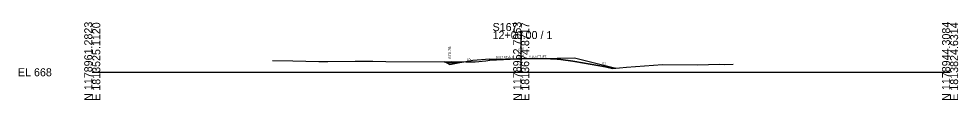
# Model space of a CAD drawing. Extents: x -26 to 6803, y -10 to 1023.
# Drawn here: x -25.7 to 302.8, y 990.3 to 1017.6 of the extents above; entities that cross this region are included whole.
import ezdxf

# ---------------------------------------------------------------- set-up
doc = ezdxf.new("R2010")
doc.units = 0
for name, color, linetype in [('Default', 7, 'Continuous'), ('RD_GPK_XS_Cell', 7, 'Continuous'), ('RD_XS_EarthShd', 7, 'Continuous'), ('RD_XS_ExGround', 7, 'Continuous'), ('RD_XS_Misc_Line', 7, 'Continuous'), ('RD_XS_Pave', 7, 'Continuous'), ('RD_XS_TieSlope', 7, 'Continuous'), ('RD_XS_TX_Elev_EX', 7, 'Continuous'), ('RD_XS_TX_Elev_PR', 7, 'Continuous'), ('RD_XS_TX_Slope', 7, 'Continuous')]:
    doc.layers.add(name, color=color, linetype=linetype)

msp = doc.modelspace()

# ---------------------------------------------------------------- linework, layer by layer
at = {"layer": 'Default'}
for p, q in [((139.04, 1004.6), (150, 1004.79)), ((150, 1004.79), (162.64, 1004.98))]:
    msp.add_line(p, q, dxfattribs=at)
at = {"layer": 'RD_GPK_XS_Cell'}
for p, q in [((150, 1000), (150, 1014.43)), ((0, 1000), (150, 1000)), ((150, 1000), (300, 1000))]:
    msp.add_line(p, q, dxfattribs=at)
at = {"layer": 'RD_XS_EarthShd'}
for p, q in [((139.04, 1004.6), (133.04, 1004.1)), ((162.64, 1004.98), (168.64, 1005.07))]:
    msp.add_line(p, q, dxfattribs=at)
at = {"layer": 'RD_XS_ExGround'}
msp.add_lwpolyline([(63.05, 1004.07), (70.12, 1004.02), (79.23, 1003.78), (82.37, 1003.76), (91.89, 1003.87), (98.12, 1003.83), (102.69, 1003.79), (123.12, 1003.66), (125.57, 1003.8), (133.91, 1003.63), (137.66, 1004.06), (139.04, 1004.21), (148.6, 1004.66), (150, 1004.73), (151.63, 1004.81), (160.21, 1004.67), (162.64, 1004.63), (163.89, 1004.51), (168.01, 1003.9), (168.77, 1003.75), (179.44, 1001.85), (181.91, 1001.36), (186.88, 1001.74), (199.38, 1002.76), (211.79, 1002.6), (219.19, 1002.78), (221.21, 1002.76), (224.14, 1002.8)], dxfattribs=at)
at = {"layer": 'RD_XS_Misc_Line'}
for points in [[(125, 1002.76), (123.19, 1003.67), (125.57, 1003.8), (130.62, 1003.7)], [(125, 1002.76), (123.19, 1003.67), (125.57, 1003.8), (130.62, 1003.7)], [(125, 1002.76), (123.19, 1003.67), (125.57, 1003.8), (130.62, 1003.7)], [(125.57, 1003.8), (130.62, 1003.7), (125, 1002.76), (123.19, 1003.67)], [(125.57, 1003.8), (130.62, 1003.7), (125, 1002.76), (123.19, 1003.67)], [(139.04, 1004.21), (139.04, 1004.6), (133.04, 1004.1), (130.62, 1003.7), (133.91, 1003.63), (137.66, 1004.06)], [(139.04, 1004.21), (139.04, 1004.6), (133.04, 1004.1), (130.62, 1003.7), (133.91, 1003.63), (137.66, 1004.06)], [(139.04, 1004.21), (139.04, 1004.6), (133.04, 1004.1), (130.62, 1003.7), (133.91, 1003.63), (137.66, 1004.06)], [(130.62, 1003.7), (133.91, 1003.63), (137.66, 1004.06), (139.04, 1004.21), (139.04, 1004.6), (133.04, 1004.1)], [(130.62, 1003.7), (133.91, 1003.63), (137.66, 1004.06), (139.04, 1004.21), (139.04, 1004.6), (133.04, 1004.1)], [(139.04, 1004.21), (139.04, 1004.6), (150, 1004.79), (162.64, 1004.98), (162.64, 1004.63), (160.21, 1004.67), (151.63, 1004.81), (150, 1004.73), (148.6, 1004.66)], [(139.04, 1004.21), (139.04, 1004.6), (150, 1004.79), (162.64, 1004.98), (162.64, 1004.63), (160.21, 1004.67), (151.63, 1004.81), (150, 1004.73), (148.6, 1004.66)], [(139.04, 1004.21), (139.04, 1004.6), (150, 1004.79), (162.64, 1004.98), (162.64, 1004.63), (160.21, 1004.67), (151.63, 1004.81), (150, 1004.73), (148.6, 1004.66)], [(150, 1004.79), (162.64, 1004.98), (162.64, 1004.63), (160.21, 1004.67), (151.63, 1004.81), (150, 1004.73), (148.6, 1004.66), (139.04, 1004.21), (139.04, 1004.6)], [(150, 1004.79), (162.64, 1004.98), (162.64, 1004.63), (160.21, 1004.67), (151.63, 1004.81), (150, 1004.73), (148.6, 1004.66), (139.04, 1004.21), (139.04, 1004.6)], [(162.64, 1004.98), (168.64, 1005.07), (183.1, 1001.45), (181.91, 1001.36), (179.44, 1001.85), (168.77, 1003.75), (168.01, 1003.9), (163.89, 1004.51), (162.64, 1004.63)], [(162.64, 1004.98), (168.64, 1005.07), (183.1, 1001.45), (181.91, 1001.36), (179.44, 1001.85), (168.77, 1003.75), (168.01, 1003.9), (163.89, 1004.51), (162.64, 1004.63)], [(162.64, 1004.98), (168.64, 1005.07), (183.1, 1001.45), (181.91, 1001.36), (179.44, 1001.85), (168.77, 1003.75), (168.01, 1003.9), (163.89, 1004.51), (162.64, 1004.63)], [(168.64, 1005.07), (183.1, 1001.45), (181.91, 1001.36), (179.44, 1001.85), (168.77, 1003.75), (168.01, 1003.9), (163.89, 1004.51), (162.64, 1004.63), (162.64, 1004.98)], [(168.64, 1005.07), (183.1, 1001.45), (181.91, 1001.36), (179.44, 1001.85), (168.77, 1003.75), (168.01, 1003.9), (163.89, 1004.51), (162.64, 1004.63), (162.64, 1004.98)]]:
    msp.add_lwpolyline(points, close=True, dxfattribs=at)
at = {"layer": 'RD_XS_Pave'}
for p, q in [((139.04, 1004.21), (139.04, 1004.6)), ((162.64, 1004.98), (162.64, 1004.63))]:
    msp.add_line(p, q, dxfattribs=at)
at = {"layer": 'RD_XS_TieSlope'}
msp.add_line((168.64, 1005.07), (183.1, 1001.45), dxfattribs=at)
at = {"layer": 'RD_XS_TX_Elev_EX'}
for p, q in [((128, 1003.26), (124, 1003.26)), ((124, 1003.26), (125, 1002.76)), ((125, 1002.76), (128, 1003.26))]:
    msp.add_line(p, q, dxfattribs=at)

# ---------------------------------------------------------------- texts
at = {"layer": 'RD_GPK_XS_Cell'}
for s, p in [('N 1178961.2823', (0, 990)), ('E 1813525.1120', (2.8, 990)), ('N 1178952.7953', (150, 990)), ('E 1813674.8717', (152.8, 990)), ('N 1178944.3084', (300, 990)), ('E 1813824.6314', (302.8, 990))]:
    msp.add_text(s, height=2.8, rotation=90, dxfattribs=at).set_placement(p)
for s, p in [('S167', (140, 1014.43)), ('12+00.00 / 1', (140, 1011.63)), ('EL 668', (-26, 998.6))]:
    msp.add_text(s, height=2.8, dxfattribs=at).set_placement(p)
at = {"layer": 'RD_XS_TX_Elev_EX'}
msp.add_text('672.73', height=0.8, rotation=90, dxfattribs=at).set_placement((149.86, 1005))
at = {"layer": 'RD_XS_TX_Elev_PR'}
for s, height, p in [('670.76', 1, (125.5, 1004.76)), ('672.79', 0.8, (150.93, 1005.46))]:
    msp.add_text(s, height=height, rotation=90, dxfattribs=at).set_placement(p)
at = {"layer": 'RD_XS_TX_Slope'}
for s, rotation, p in [('0.017 FT./FT.', 0.9888, (141.15, 1004.89)), ('0.015 FT./FT.', 0.8484, (152.86, 1005.08)), ('6:1', 14.0362, (131.06, 1004)), ('4:1', 345.9638, (178.19, 1002.94))]:
    msp.add_text(s, height=0.75, rotation=rotation, dxfattribs=at).set_placement(p)

doc.saveas('drawing.dxf')
